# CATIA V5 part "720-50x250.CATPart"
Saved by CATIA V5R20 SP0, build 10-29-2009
Part number: 720-50x250
Definition: NONE
Nomenclature: 720-50x250
Source: Unknown
Description: 720-50x250
Bounding box of the stored display mesh (mm): x 0 to 250, y -25 to 25, z -25 to 25
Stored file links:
  C:\Users\Utente\Desktop\IO LAVORO\3D X SITO CF\X SITO\720\720-50x250.CATPart
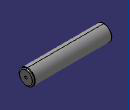
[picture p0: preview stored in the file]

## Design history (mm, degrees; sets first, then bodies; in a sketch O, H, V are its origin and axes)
Body1 "720-50x250" (main body)
  Solid1: solid without history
